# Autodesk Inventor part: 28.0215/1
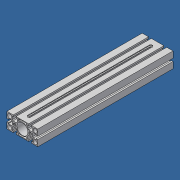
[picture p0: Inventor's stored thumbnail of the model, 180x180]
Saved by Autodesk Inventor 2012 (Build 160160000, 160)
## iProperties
Created: 2011-05
Part Number: 28.0215/1
Material: Aluminum-6061
Description: L = TRAVEL +3.543", TA4,  MACHINE TO 28.0215/1
Document SubType Name: Modeling
Designer: Administrator
Stock Number: 20.1017 PROFILE 45X90 S
Density: 2.71 g/cm^3
Vendor: F
Mass: 1550.21 g
Surface Area: 3547.28 cm^2
Volume: 572.033 cm^3
FINISH: CLEAR ANODIZED
Author: Administrator
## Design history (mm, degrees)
sketch "Sketch1"
  geometry: L1 (11.7, 20.5)-(11.7, 15.701) reference; L2 (-11.7, 15.701)-(-11.7, 20.5) reference; L3 (-11.7, 20.5)-(11.7, 20.5) reference; L4 (-11.7, -20.5)-(-11.7, -15.701) reference; L5 (11.7, -15.701)-(11.7, -20.5) reference; L6 (11.7, -20.5)-(-11.7, -20.5) reference; L7 (26.6, 22.5)-(26.6, 18) reference; L8 (27.1, 18)-(29.3, 18) reference; L9 (29.3, 18)-(29.3, 9.5) reference; L10 (29.3, 9.5)-(27, 7.2) reference; L11 (27, 7.2)-(18, 7.2) reference; L12 (18, 7.2)-(15.7, 9.5) reference; L13 (15.7, 9.5)-(15.7, 18) reference; L14 (18.4, 18)-(18.4, 22.5) reference; L15 (-18.4, 22.5)-(-18.4, 18) reference; L16 (-15.7, 18)-(-15.7, 9.5) reference; L17 (-15.7, 9.5)-(-18, 7.2) reference; L18 (-18, 7.2)-(-27, 7.2) reference; L19 (-27, 7.2)-(-29.3, 9.5) reference; L20 (-29.3, 9.5)-(-29.3, 18) reference; L21 (-29.3, 18)-(-27.1, 18) reference; L22 (-26.6, 18)-(-26.6, 22.5) reference; L23 (-45, 4.1)-(-40.5, 4.1) reference; L24 (-40.5, 6.8)-(-32, 6.8) reference; L25 (-32, 6.8)-(-29.7, 4.5) reference; L26 (-29.7, 4.5)-(-29.7, -4.5) reference; L27 (-29.7, -4.5)-(-32, -6.8) reference; L28 (-32, -6.8)-(-40.5, -6.8) reference; L29 (-40.5, -6.8)-(-40.5, -4.6) reference; L30 (-40.5, -4.1)-(-45, -4.1) reference; L31 (-45, -22.5)-(-45, -4.4) reference; L32 (-26.6, -22.5)-(-26.6, -18) reference; L33 (-27.1, -18)-(-29.3, -18) reference; L34 (-29.3, -18)-(-29.3, -9.5) reference; L35 (-29.3, -9.5)-(-27, -7.2) reference; L36 (-27, -7.2)-(-18, -7.2) reference; L37 (-18, -7.2)-(-15.7, -9.5) reference; L38 (-15.7, -9.5)-(-15.7, -18) reference; L39 (-18.4, -18)-(-18.4, -22.5) reference; L40 (18.4, -22.5)-(18.4, -18) reference; L41 (15.7, -18)-(15.7, -9.5) reference; L42 (15.7, -9.5)-(18, -7.2) reference; L43 (18, -7.2)-(27, -7.2) reference; L44 (27, -7.2)-(29.3, -9.5) reference; L45 (29.3, -9.5)-(29.3, -18) reference; L46 (29.3, -18)-(27.1, -18) reference; L47 (26.6, -18)-(26.6, -22.5) reference; L48 (45, -22.5)-(26.9, -22.5) reference; L49 (45, -4.4)-(45, -22.5) reference; L50 (45, -4.1)-(40.5, -4.1) reference; L51 (40.5, -4.6)-(40.5, -6.8) reference; L52 (40.5, -6.8)-(32, -6.8) reference; L53 (32, -6.8)-(29.7, -4.5) reference; L54 (29.7, -4.5)-(29.7, 4.5) reference; L55 (29.7, 4.5)-(32, 6.8) reference; L56 (32, 6.8)-(40.5, 6.8) reference; L57 (40.5, 4.1)-(45, 4.1) reference; L58 (26.9, 22.5)-(45, 22.5) reference; L59 (-45, -4.4)-(-45, -4.1) reference; L60 (-45, 4.1)-(-45, 22.5) reference; L61 (-40.5, -4.6)-(-40.5, -4.1) reference; L62 (-40.5, 4.1)-(-40.5, 6.8) reference; L63 (-27.1, 18)-(-26.6, 18) reference; L64 (-18.4, 18)-(-15.7, 18) reference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; C1 r 3.75 at (22.5, 0) reference; C2 r 3.75 at (-22.5, 0) reference; C3 r 16 at (0, 0) reference; C4 r 5.85 at (-37.15, -14.65) reference; C5 r 5.85 at (-37.15, 14.65) reference; C6 r 5.85 at (37.15, -14.65) reference; C7 r 5.85 at (37.15, 14.65) reference; A1 r 1 centre (10.7, 15.701) between (10.137, 14.874) and (11.7, 15.701) reference; A2 r 18 centre (0, 0) between (10.137, 14.874) and (-10.137, 14.874) reference; A3 r 1 centre (-10.7, 15.701) between (-11.7, 15.701) and (-10.137, 14.874) reference; A4 r 1 centre (-10.7, -15.701) between (-10.137, -14.874) and (-11.7, -15.701) reference; A5 r 18 centre (0, 0) between (-10.137, -14.874) and (10.137, -14.874) reference; A6 r 1 centre (10.7, -15.701) between (11.7, -15.701) and (10.137, -14.874) reference
  constraints: 164 end point, 36 horizontal, 34 vertical, 13 centre point, 12 point on circle, 126 other
extrude "Extrusion1" new body sketch "Sketch1" stored distance "d0" = 394.8 (computed from TRAVEL); taper "d1" = 0 deg
sketch "Sketch2"
  geometry: L1 (0, 0)-(36.8, 0) reference; L2 (36.8, 394.8)-(0, 394.8) reference; L3 (0, 0)-(0, 394.8) reference; L4 (13.65, 374.8)-(13.65, 20); L5 (23.15, 20)-(23.15, 374.8); A1 r 4.75 centre (18.4, 374.8) between (23.15, 374.8) and (13.65, 374.8); A2 r 4.75 centre (18.4, 20) between (13.65, 20) and (23.15, 20); 3 further points
  constraints: 4 end point, 4 point on circle, 4 tangent, 2 centre point, 2 midpoint, 2 vertical alignment, 1 parallel
  dimensions: "d2" = 4.75 radius of A1; "d3" = 20 distance from line of A1.centre L2; "d4" = 20 distance from line of L1 A2.centre (= d3)
extrude "Extrusion2" cut sketch "Sketch2" distance "d5" = 12.7; taper "d6" = 0 deg
thread "Thread1" dims "d7" = 25.4, "d8" = 0
thread "Thread2" dims "d9" = 25.4, "d10" = 0
thread "Thread3" dims "d11" = 25.4, "d12" = 0
thread "Thread4" dims "d13" = 25.4, "d14" = 369.316
body "Solid1"
other parameters: "TRAVEL" = 304.8 [user parameter; used in 1 equation term]
